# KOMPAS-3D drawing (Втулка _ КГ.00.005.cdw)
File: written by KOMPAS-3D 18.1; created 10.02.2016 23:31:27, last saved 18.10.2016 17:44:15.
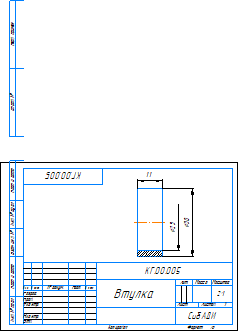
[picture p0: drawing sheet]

Sheet 1: A5, landscape

Document properties: Автор: Alexey; Полное имя файла: D:\АТТ-21Т1\! Разработка сборочных чертежей и спец\Рабочие чертежи\Втулка _ КГ.00.005.cdw

Title block, sheet 1: Наименование: Втулка; designation: КГ.00.005; scale: 2:1; Количество листов документа: 1; organisation: СибАДИ; Форматы листов документа: A5; stored path: C:\Users\Alexey\Desktop\СБ спец\Втулка _ КГ.00.005.cdw

Views: Вид 1
Dimensions and other numbers on the sheet: 25; 30; 11; 2:1; 1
